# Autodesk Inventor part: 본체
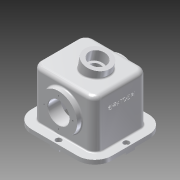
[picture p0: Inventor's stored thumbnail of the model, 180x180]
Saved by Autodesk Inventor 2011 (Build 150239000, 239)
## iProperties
Created: 2014-11
Part Number: 본체
Material: 알루미늄-6061
Document SubType Name: Modeling
Designer: Administrator
Mass: 2879.08 g
Surface Area: 2085.81 cm^2
Volume: 1062.39 cm^3
Density: 2.71 g/cm^3
Author: Administrator
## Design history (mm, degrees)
sketch "스케치1"
  geometry: L1 (0, 0)-(-98, 0); L2 (-98, 0)-(-98, 87); L3 (-98, 87)-(98, 87); L4 (98, 87)-(98, -87); L5 (98, -87)-(-98, -87); L6 (-98, -87)-(-98, 87)
  constraints: 12 end point, 2 horizontal, 2 parallel, 2 perpendicular
extrude "돌출1" new body sketch "스케치1" distance "d0" = 10; taper "d1" = 0 deg
sketch "스케치2"
  geometry: L1 (98, -87)-(-98, -87) reference; L2 (0, 0)-(-76, 0); L3 (-76, 0)-(-76, 65); L4 (-76, 65)-(76, 65); L5 (76, 65)-(76, -65); L6 (76, -65)-(-76, -65); L7 (-76, -65)-(-76, 65)
  constraints: 12 end point, 3 parallel, 2 perpendicular, 1 horizontal
extrude "돌출2" join sketch "스케치2" distance "d2" = 118; taper "d3" = 0 deg
sketch "스케치3"
  geometry: L1 (76, 0)-(76, -65); L2 (76, -65)-(-76, -65) reference; L3 (-76, -65)-(-76, 65) reference; L4 (-76, 65)-(76, 65) reference; L5 (76, 65)-(76, -65) reference; L6 (-66, -55)-(66, -55); L7 (66, -55)-(66, 55); L8 (66, 55)-(-66, 55); L9 (-66, 55)-(-66, -55); 1 further point
  constraints: 18 end point, 4 parallel, 3 horizontal, 2 perpendicular, 2 vertical, 3 other
  dimensions: "d4" = 10 distance between parallel lines of L2 L6
extrude "돌출3" cut sketch "스케치3" distance "d5" = 118; taper "d6" = 0 deg
sketch "스케치5"
  geometry: L1 (152, 0)-(152, 118) reference; L2 (76, -10)-(76, 58); C1 r 45.5 at (76, 58)
  constraints: 2 end point, 1 centre point, 1 coincident, 1 parallel
extrude "돌출4" join sketch "스케치5" distance "d7" = 12; taper "d8" = 0 deg
sketch "스케치6"
  geometry: L1 (87, 10)-(87, 0) reference; L2 (87, 0)-(55, 0) reference; L3 (55, 0)-(55, 118) reference; L4 (55, 118)-(-55, 118) reference; L5 (-55, 118)-(-55, 0) reference; L6 (-55, 0)-(-87, 0) reference; L7 (-87, 0)-(-87, 10) reference; L8 (-87, 10)-(-65, 10) reference; L9 (-65, 10)-(-65, 22.5) reference; L10 (-65, 22.5)-(-77, 22.5) reference; L11 (-77, 22.5)-(-77, 113.5) reference; L12 (-77, 113.5)-(-65, 113.5) reference; L13 (-65, 113.5)-(-65, 128) reference; L14 (-65, 128)-(65, 128) reference; L15 (65, 128)-(65, 10) reference; L16 (65, 10)-(87, 10) reference; L17 (-65, 113.5)-(-55, 113.5); L18 (-65, 22.5)-(-55, 22.5); L19 (-55, 113.5)-(-55, 22.5); L20 (-55, 68)-(-45, 68); L21 (-45, 68)-(-45, 103.5); L22 (-45, 103.5)-(-55, 113.5); L23 (-55, 68)-(-92.223, 68); 1 further point
  constraints: 14 end point, 4 perpendicular, 2 point on line, 1 midpoint, 1 parallel
revolve "회전1" sketch "스케치6" stored, may be unused: angle "d9" = 90 deg
sketch "스케치7"
  geometry: C1 r 45.5 at (0, 0) reference; C2 r 26 at (0, 0); 1 further point
  constraints: 1 centre point, 1 coincident
extrude "돌출5" cut sketch "스케치7" distance "d10" = 50; taper "d11" = 0 deg
sketch "스케치8"
  geometry: L1 (98, 10)-(98, 0) reference; L2 (98, 0)-(66, 0) reference; L3 (66, 0)-(66, 118) reference; L4 (66, 118)-(-66, 118) reference; L5 (-66, 118)-(-66, 0) reference; L6 (-66, 0)-(-98, 0) reference; L7 (-98, 0)-(-98, 10) reference; L8 (-98, 10)-(-76, 10) reference; L9 (-76, 10)-(-76, 128) reference; L10 (-76, 128)-(76, 128) reference; L11 (76, 128)-(76, 10) reference; L12 (76, 10)-(98, 10) reference; L13 (0, 0)-(0, 68); L14 (0, 68)-(-17.88, 152.121); L15 (-17.88, 152.121)-(12.442, 158.566); L16 (12.442, 158.566)-(21.911, 114.02); L17 (21.911, 114.02)-(-8.412, 107.575)
  constraints: 10 end point, 4 perpendicular, 1 point on line
revolve "회전2" sketch "스케치8" stored, may be unused: angle "d12" = 90 deg
sketch "스케치9"
  geometry: L1 (-48.431, 37.545)-(26.592, 37.545); L2 (26.592, 37.545)-(26.592, -33.811); L3 (26.592, -33.811)-(-48.431, -33.811); L4 (-48.431, -33.811)-(-48.431, 37.545); 1 further point
  constraints: 8 end point, 2 parallel, 1 horizontal, 1 perpendicular
extrude "돌출6" cut sketch "스케치9" distance "d13" = 50; taper "d14" = 0 deg
sketch "스케치10"
  geometry: C1 r 31 at (0, 0) reference; C2 r 21 at (0, 0); 1 further point
  constraints: 1 centre point, 1 coincident
extrude "돌출7" cut sketch "스케치10" distance "d15" = 25; taper "d16" = 0 deg
sketch "스케치11"
  geometry: C1 r 21 at (0, 0) reference; C2 r 15 at (0, 0); 1 further point
  constraints: 1 centre point, 1 coincident
extrude "돌출8" cut sketch "스케치11" distance "d17" = 25; taper "d18" = 0 deg
chamfer "모따기1" distance "d19" = 1; stored, may be unused: second distance "d20" = 2, angle "d21" = 45 deg
fillet "모깎기1" dims "d22" = 0.3
sketch "스케치12"
  geometry: L1 (98, 87)-(-98, 87) reference; L2 (0, 0)-(0, 87); L3 (0, 87)-(-11, 87); L4 (-11, 87)-(-11, 77); L5 (-11, 87)-(11, 87); L6 (11, 87)-(11, 77); L7 (-11, 77)-(-11, 87); L8 (-11, 87)-(11, 87); L9 (11, 87)-(11, 67); L10 (11, 67)-(-11, 67); L11 (-11, 67)-(-11, 87)
  constraints: 20 end point, 3 parallel, 3 perpendicular, 2 horizontal, 1 midpoint, 1 point on line
extrude "돌출9" join sketch "스케치12" distance "d23" = 5; taper "d24" = 0 deg
sketch "스케치13"
  geometry: L1 (-98, 87)-(-98, -87) reference; L2 (0, 0)-(-98, 0); L3 (-98, 0)-(-98, 11); L4 (-98, 1)-(-98, 11); L5 (-98, 11)-(-78, 11); L6 (-78, 11)-(-78, -11); L7 (-78, -11)-(-98, -11); L8 (-98, -11)-(-98, 11)
  constraints: 14 end point, 2 parallel, 1 horizontal, 1 midpoint, 1 perpendicular, 1 point on line
extrude "돌출10" join sketch "스케치13" distance "d25" = 5; taper "d26" = 0 deg
sketch "스케치14"
  geometry: L1 (98, -87)-(-98, -87) reference; L2 (0, 0)-(0, -88); L3 (0, 0)-(-88, 0); C1 r 7 at (-88, 0)
  constraints: 4 end point, 2 perpendicular, 1 centre point, 1 coincident
extrude "돌출11" cut sketch "스케치14" distance "d27" = 8.6; taper "d28" = 0 deg
sketch "스케치15"
  geometry: C1 r 7 at (0, 0) reference; C2 r 4.5 at (0, 0); 1 further point
  constraints: 1 centre point, 1 coincident
extrude "돌출12" cut sketch "스케치15" stored distance "d29" = 8.6; taper "d30" = 0 deg
sketch "스케치16"
  geometry: L1 (-11, -67)-(-11, -87) reference; L2 (11, -87)-(-11, -87) reference; L3 (-11, -87)-(-11, -67) reference; L4 (-11, -67)-(11, -67) reference; L5 (11, -67)-(11, -87) reference; L6 (0, -67)-(0, -87); L7 (-11, -77)-(11, -77); C1 r 7 at (0, -77); 1 further point
  constraints: 5 midpoint, 4 end point, 1 centre point
extrude "돌출13" cut sketch "스케치16" distance "d31" = 8.6; taper "d32" = 0 deg
sketch "스케치17"
  geometry: C1 r 7 at (0, 0) reference; C2 r 4.5 at (0, 0); 1 further point
  constraints: 1 centre point, 1 coincident
extrude "돌출14" cut sketch "스케치17" stored distance "d33" = 8.6; taper "d34" = 0 deg
sketch "스케치18"
  geometry: L1 (0, 0)-(0, 35); C1 r 27 at (0, 0) reference; C2 r 2.407 at (0, 35); 1 further point
  constraints: 2 coincident, 2 end point, 1 centre point, 1 vertical, 1 vertical alignment, 2 other
hole "Hole1" sketch "스케치18" at (0, 35) diameter "d35" = 3.242; stored, may be unused: countersink angle "d39" = 90 deg, drill point angle "d41" = 118 deg; dims "d36" = 13, "d37" = 4, "d38" = 2, "d40" = 16
fillet "모깎기2" dims "d45" = 42
fillet "모깎기3" dims "d46" = 20
fillet "모깎기4" dims "d47" = 10
fillet "모깎기5" dims "d48" = 10
fillet "모깎기6" dims "d49" = 3
fillet "모깎기7" dims "d50" = 3
fillet "모깎기8" dims "d51" = 3
fillet "모깎기9" dims "d52" = 3
fillet "모깎기10" dims "d53" = 3
sketch "스케치19"
  geometry: 2 further points
  constraints: 1 other
feature "엠보싱1" sketch "스케치19" dims "d4" = 10, "d54" = 1, "d55" = 0
fillet "모깎기11" dims "d56" = 3
node "솔리드1"
mirror "대칭1"
mirror "대칭2"
mirror "대칭3"
mirror "대칭4"
mirror "대칭5"
pattern_circular "원형 패턴1" dims angle "d43" = 360 deg
mirror "대칭6"
node "투영된 루프1"
node "절단 모서리 투영2"
node "절단 모서리 투영3"
